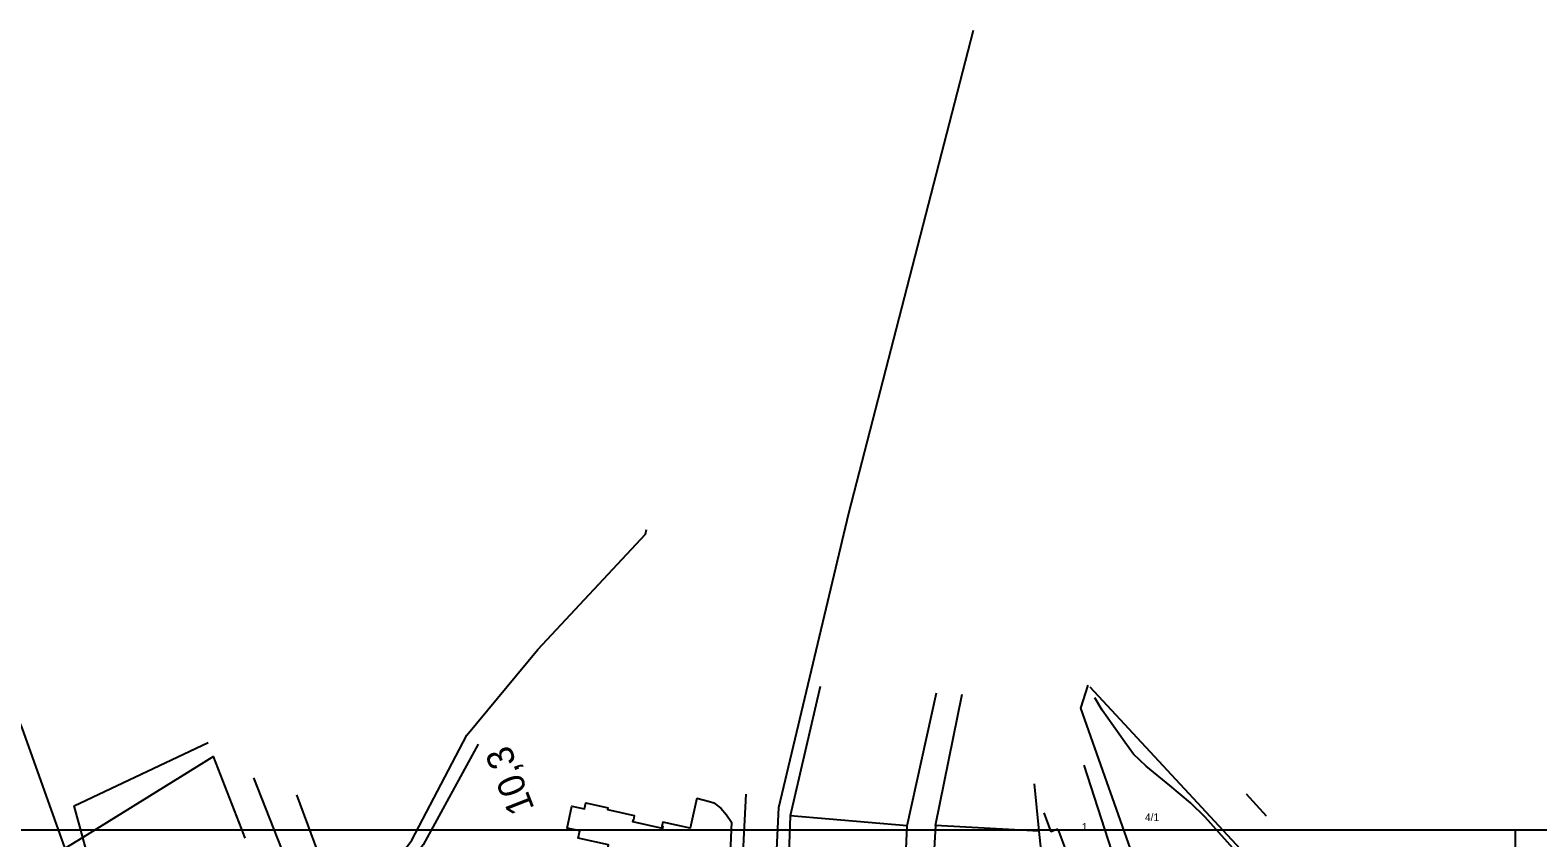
# Model space of a CAD drawing. Extents: x -553916 to -552953, y -1067470 to -1066637.
# Drawn here: x -553633.4 to -553294.9, y -1066818.1 to -1066636.6 of the extents above; entities that cross this region are included whole.
import ezdxf

# ---------------------------------------------------------------- set-up
doc = ezdxf.new("R2010")
doc.units = 0
for name, color, linetype in [('Hranice parcel', 7, 'Continuous'), ('Kolej', 7, 'Continuous'), ('Návěst místo trati', 7, 'Continuous'), ('Parcelní čísla', 7, 'Continuous'), ('Vnitřní kresba', 7, 'Continuous'), ('Vrstva 1', 7, 'Continuous')]:
    doc.layers.add(name, color=color, linetype=linetype)

msp = doc.modelspace()

# ---------------------------------------------------------------- linework, layer by layer
at = {"layer": 'Hranice parcel'}
for p, q in [((-553456.02, -1066784.1), (-553462.79, -1066813.1)), ((-553436.47, -1066815.36), (-553429.88, -1066785.49)), ((-553430.14, -1066815.28), (-553424.14, -1066785.8)), ((-553395.45, -1066784.17), (-553361.7, -1066820.54)), ((-553592.22, -1066799.8), (-553621.6, -1066817.99)), ((-553407.99, -1066805.97), (-553406.9, -1066816.6)), ((-553407.99, -1066805.97), (-553406.9, -1066816.6)), ((-553473.84, -1066830.72), (-553472.63, -1066808.29)), ((-553360.35, -1066808.19), (-553355.86, -1066813.11)), ((-553462.79, -1066813.1), (-553463.9, -1066843.58)), ((-553436.47, -1066815.36), (-553462.79, -1066813.1)), ((-553362.67, -1066821.17), (-553369.61, -1066813.45)), ((-553437.72, -1066844.45), (-553436.47, -1066815.36)), ((-553430.14, -1066815.28), (-553430.74, -1066826)), ((-553406.9, -1066816.6), (-553430.14, -1066815.28)), ((-553406.9, -1066816.6), (-553405.9, -1066826.43)), ((-553406.9, -1066816.6), (-553405.9, -1066826.43)), ((-553621.6, -1066817.99), (-553625.66, -1066820.5)), ((-553617.57, -1066832.95), (-553621.6, -1066817.99))]:
    msp.add_line(p, q, dxfattribs=at)
for points in [[(-553477.08, -1066903.52), (-553471.25, -1066891.92), (-553468.41, -1066870.82), (-553466.8, -1066842.82), (-553465.31, -1066811.26), (-553449.58, -1066745.18), (-553421.6, -1066636.65)], [(-553562.46, -1066838.44), (-553547.69, -1066818.62), (-553535.38, -1066795.04), (-553519.42, -1066775.8), (-553495.28, -1066749.85), (-553495.01, -1066748.81)], [(-553643.88, -1066774.03), (-553635.29, -1066793.34), (-553625.66, -1066820.5)], [(-553384.58, -1066825.61), (-553397.51, -1066788.92), (-553395.83, -1066783.77)], [(-553369.61, -1066813.45), (-553372.88, -1066810.21), (-553377.49, -1066806.31), (-553382.84, -1066801.95), (-553385.65, -1066799.3), (-553387.62, -1066796.6), (-553392.69, -1066789.37), (-553394.35, -1066786.66)], [(-553621.6, -1066817.99), (-553623.51, -1066810.9), (-553593.45, -1066796.65)], [(-553532.8, -1066797.02), (-553545.17, -1066819.67), (-553553.48, -1066830.52), (-553560.01, -1066844.54)], [(-553389.03, -1066825.78), (-553390.55, -1066821.01), (-553396.74, -1066801.73)], [(-553483.73, -1066809.15), (-553485.25, -1066815.92), (-553491.35, -1066814.56), (-553491.57, -1066815.51), (-553491.38, -1066815.55), (-553491.47, -1066815.96), (-553498.12, -1066814.47), (-553498.04, -1066814), (-553497.9, -1066814.03), (-553497.69, -1066813.13), (-553503.74, -1066811.77), (-553503.64, -1066811.31)], [(-553483.73, -1066809.15), (-553480.88, -1066809.9), (-553479.9, -1066810.22), (-553478.34, -1066811.42), (-553477.07, -1066812.9), (-553475.95, -1066814.54), (-553476.7, -1066832.08)], [(-553500.33, -1066835.91), (-553506.92, -1066834.42), (-553503.58, -1066819.65), (-553510.37, -1066818.12), (-553510, -1066816.53), (-553512.88, -1066815.92), (-553511.82, -1066810.98), (-553508.93, -1066811.58), (-553508.63, -1066810.19), (-553503.64, -1066811.31)]]:
    msp.add_lwpolyline(points, dxfattribs=at)
at = {"layer": 'Kolej'}
msp.add_lwpolyline([(-553503.32, -1067065.81), (-553502.68, -1067054.03), (-553502.76, -1067041.5), (-553503.63, -1067029.06), (-553504.76, -1067019.97), (-553506.18, -1067011.39), (-553508.33, -1067001.39), (-553510.95, -1066991.62), (-553512.92, -1066985.29), (-553515.65, -1066977.35), (-553517.42, -1066972.53), (-553519.16, -1066967.95), (-553522.89, -1066958.38), (-553529.1, -1066942.55), (-553538.69, -1066918.11), (-553542.91, -1066907.33), (-553546.69, -1066897.68), (-553555.03, -1066876.44), (-553564.64, -1066851.89), (-553574.24, -1066827.43), (-553583.19, -1066804.62)], dxfattribs=at)
at = {"layer": 'Vnitřní kresba'}
for p, q in [((-553405.84, -1066812.43), (-553404.21, -1066816.73)), ((-553402.7, -1066816.16), (-553404.21, -1066816.73)), ((-553402.7, -1066816.16), (-553399.76, -1066823.95))]:
    msp.add_line(p, q, dxfattribs=at)
at = {"layer": 'Vrstva 1'}
for p, q in [((-553573.62, -1066808.38), (-553562.46, -1066838.44)), ((-553794.11, -1066816.27), (-552953.11, -1066816.27))]:
    msp.add_line(p, q, dxfattribs=at)
for points in [[(-553585.12, -1066818.17), (-553585.42, -1066817.3), (-553592.22, -1066799.8)], [(-553300, -1066816.27), (-553300, -1067100), (-553800, -1067100), (-553800, -1066816.27)]]:
    msp.add_lwpolyline(points, dxfattribs=at)

# ---------------------------------------------------------------- texts
at = {"layer": 'Návěst místo trati'}
msp.add_text('10,3', height=6, rotation=111.396, dxfattribs=at).set_placement((-553520.11, -1066811.5))
at = {"layer": 'Parcelní čísla'}
for s, p in [('4/1', (-553383.1, -1066814.3)), ('1', (-553397.3, -1066816.47))]:
    msp.add_text(s, height=1.7, dxfattribs=at).set_placement(p)

doc.saveas('drawing.dxf')
